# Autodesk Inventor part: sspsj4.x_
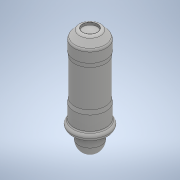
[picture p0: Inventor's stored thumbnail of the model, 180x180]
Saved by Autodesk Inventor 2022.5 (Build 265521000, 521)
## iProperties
Created: 2018-04
Part Number: sspsj4.x_
Material: 一般
Document SubType Name: Modeling
Designer: imaocorp
Density: 1 g/cm^3
Appearance: 既定
Sending System: SOLIDWORKS 2016-2016286
MC: AMD64
MC_MODEL: AMD64 Family 21 Model 2 Stepping 0, AuthenticAMD
OS: Windows_NT
FRU: Parasolid Version 28.0, build 224,  7-29-2016
FORMAT: text
GUISE: transmit
KEY: sspsj4
FILE: sspsj4.x_t
DATE: Wed Apr 25 10:15:49 2018
Author: imaocorp
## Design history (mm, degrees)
feature "Base1"
node "ソリッド1"
